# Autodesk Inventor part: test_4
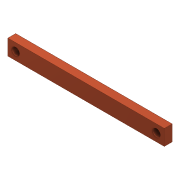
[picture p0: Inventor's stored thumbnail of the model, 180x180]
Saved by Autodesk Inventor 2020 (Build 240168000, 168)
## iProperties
Created: 2021-01
Part Number: test_4
Material: Miedź
Document SubType Name: Modeling
Designer: Home
Mass: 42.9446 g
Surface Area: 31.7854 cm^2
Volume: 4.80365 cm^3
Density: 8.94 g/cm^3
Appearance: Miedź — satynowa
Author: Home
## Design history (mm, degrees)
sketch "Szkic1"
  geometry: L1 (-50, -5)-(50, -5); L2 (50, -5)-(50, 5); L3 (50, 5)-(-50, 5); L4 (-50, 5)-(-50, -5); L5 (-50, -5)-(50, 5); L6 (50, -5)-(-50, 5); C1 r 2.5 at (-45, 0); C2 r 2.5 at (45, 0); 3 further points
  constraints: 12 end point, 4 midpoint, 2 centre point, 2 horizontal alignment, 2 parallel, 1 equal radius, 1 horizontal, 1 perpendicular
  dimensions: "d0" = 100 distance of L3.end L2.end; "d1" = 10 distance of L1.end L2.end; "d2" = 5 diameter of C1; "d3" = 45 distance of point (0, 0) C1.centre; "d4" = 45 distance of point (0, 0) C2.centre
extrude "Wyciągnięcie proste1" new body sketch "Szkic1" distance "d5" = 5; taper "d6" = 0 deg
node "Bryła1"
